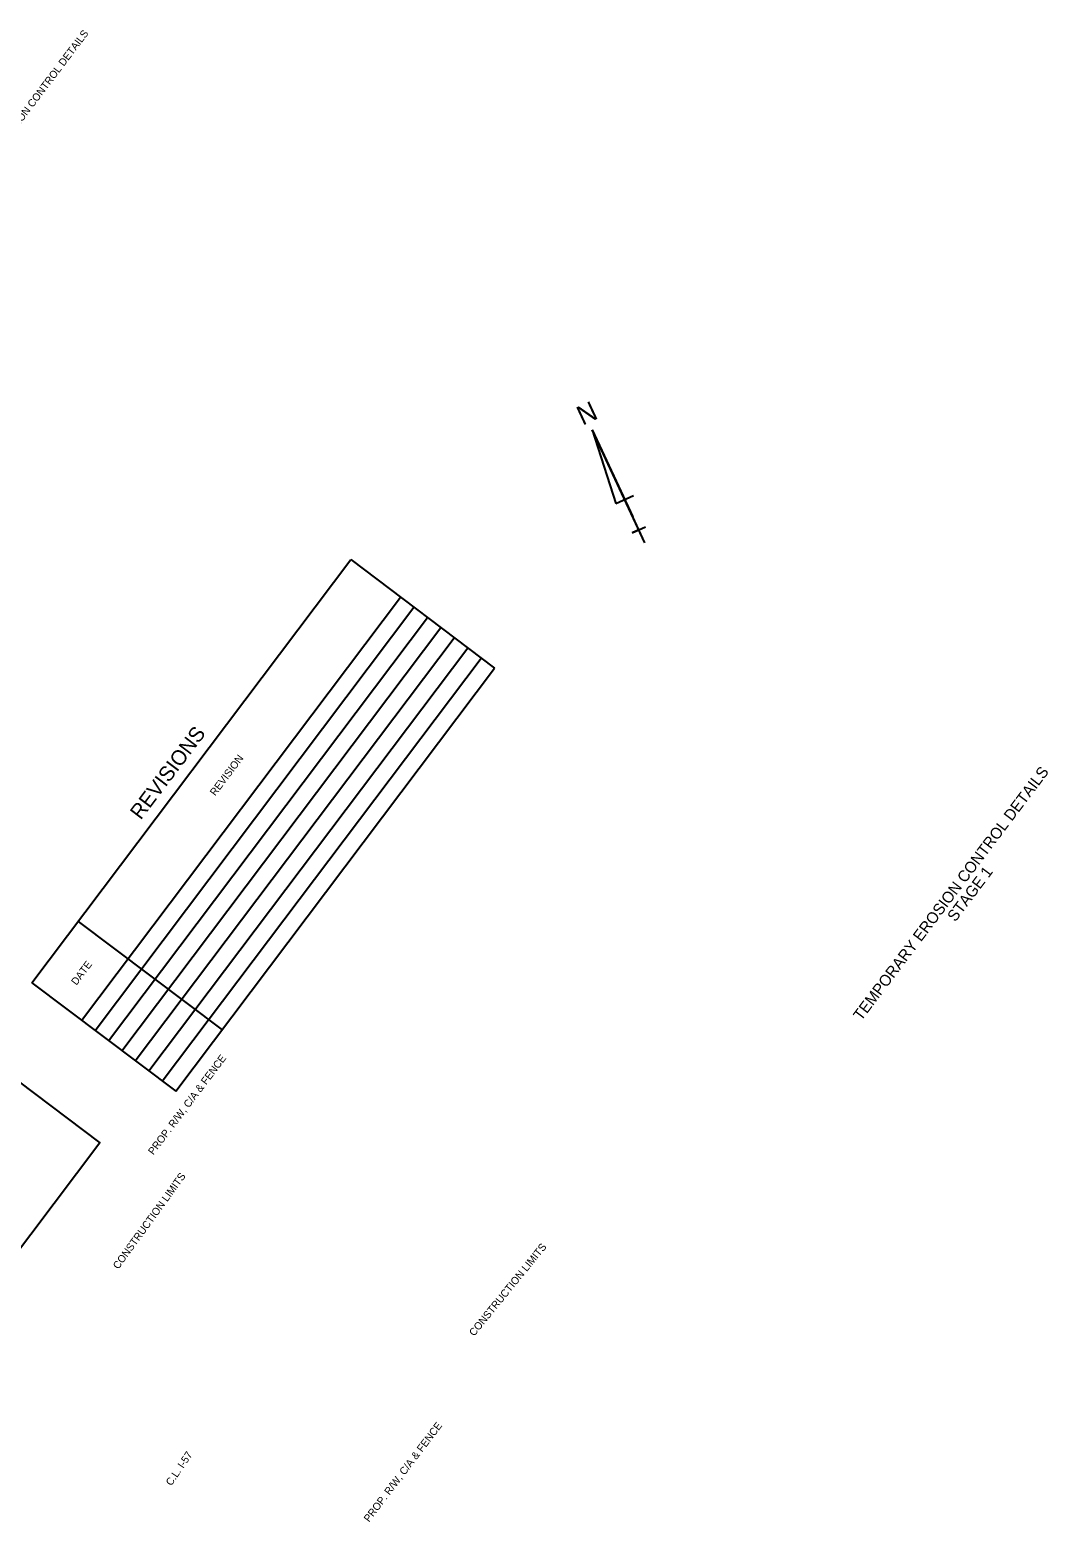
# Model space of a CAD drawing. Extents: x 1713742 to 1715480, y 763715 to 765350.
# Drawn here: x 1714663 to 1715480, y 764141 to 765350 of the extents above; entities that cross this region are included whole.
import ezdxf

# ---------------------------------------------------------------- set-up
doc = ezdxf.new("R2010")
doc.units = 0
for name, color, linetype in [('1', 7, 'Continuous'), ('63', 7, 'Continuous'), ('Default', 7, 'Continuous'), ('G-ANNO-TEXT', 7, 'Continuous'), ('R_Draft', 7, 'Continuous')]:
    doc.layers.add(name, color=color, linetype=linetype)

msp = doc.modelspace()

# ---------------------------------------------------------------- linework, layer by layer
at = {"layer": '1'}
msp.add_lwpolyline([(1714362.5, 764230), (1714601.2, 764546.8), (1714719.3, 764457.8), (1714480.6, 764141)], close=True, dxfattribs=at)
at = {"layer": '63'}
for p, q in [((1715156.4, 764939), (1715114.2, 765029.6)), ((1715114.2, 765029.6), (1715146.7, 764959.9)), ((1715114.2, 765029.6), (1715133.2, 764970.6)), ((1715133.2, 764970.6), (1715147.2, 764977.1)), ((1715146.3, 764947), (1715156.8, 764951.9)), ((1715156.4, 764939), (1715146.7, 764959.9)), ((1715151.6, 764949.4), (1715146.3, 764947)), ((1715156.4, 764939), (1715151.6, 764949.4))]:
    msp.add_line(p, q, dxfattribs=at)
at = {"layer": 'Default'}
for p, q in [((1714664.7, 764586.2), (1714920.5, 764925.6)), ((1714920.5, 764925.6), (1715035.9, 764838.6)), ((1714704.6, 764556.1), (1714960.4, 764895.5)), ((1714715.4, 764547.9), (1714971.2, 764887.4)), ((1714726.2, 764539.8), (1714982, 764879.2)), ((1714737, 764531.7), (1714992.7, 764871.1)), ((1714737, 764531.7), (1714992.7, 764871.1)), ((1714747.7, 764523.6), (1715003.5, 764863)), ((1714758.5, 764515.5), (1715014.3, 764854.9)), ((1714769.3, 764507.3), (1715025.1, 764846.7)), ((1714780.1, 764499.2), (1715035.9, 764838.6)), ((1714780.1, 764499.2), (1715035.9, 764838.6)), ((1714701.9, 764635.5), (1714817.3, 764548.6)), ((1714664.7, 764586.2), (1714780.1, 764499.2))]:
    msp.add_line(p, q, dxfattribs=at)

# ---------------------------------------------------------------- texts
at = {"layer": '63'}
msp.add_text('N', height=15.4, rotation=25, dxfattribs=at).set_placement((1715106.4, 765033))
at = {"layer": 'Default'}
for s, height, p in [('REVISIONS', 12, (1714752.1, 764716.3)), ('REVISION', 6, (1714811.8, 764735.7)), ('DATE', 6, (1714700.5, 764583.8))]:
    msp.add_text(s, height=height, rotation=53, dxfattribs=at).set_placement(p)
at = {"layer": 'G-ANNO-TEXT'}
for s, height, p in [('TEMPORARY EROSION CONTROL DETAILS', 6, (1714609.9, 765214.1)), ('TEMPORARY EROSION CONTROL DETAILS', 9, (1715330, 764555.1)), ('STAGE 1', 9, (1715405.4, 764634.6))]:
    msp.add_text(s, height=height, rotation=53, dxfattribs=at).set_placement(p)
at = {"layer": 'R_Draft'}
for s, rotation, p in [('PROP. R/W, C/A & FENCE', 52.9898, (1714762.2, 764447.7)), ('CONSTRUCTION LIMITS', 54.1085, (1714734.1, 764356)), ('CONSTRUCTION LIMITS', 50.8974, (1715019.5, 764302.3)), ('PROP. R/W, C/A & FENCE', 52.8258, (1714935.2, 764153.2)), ('C.L. I-57', 55.7863, (1714776.6, 764182.3))]:
    msp.add_text(s, height=6, rotation=rotation, dxfattribs=at).set_placement(p)

doc.saveas('drawing.dxf')
